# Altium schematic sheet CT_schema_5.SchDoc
size 278 x 170 mm
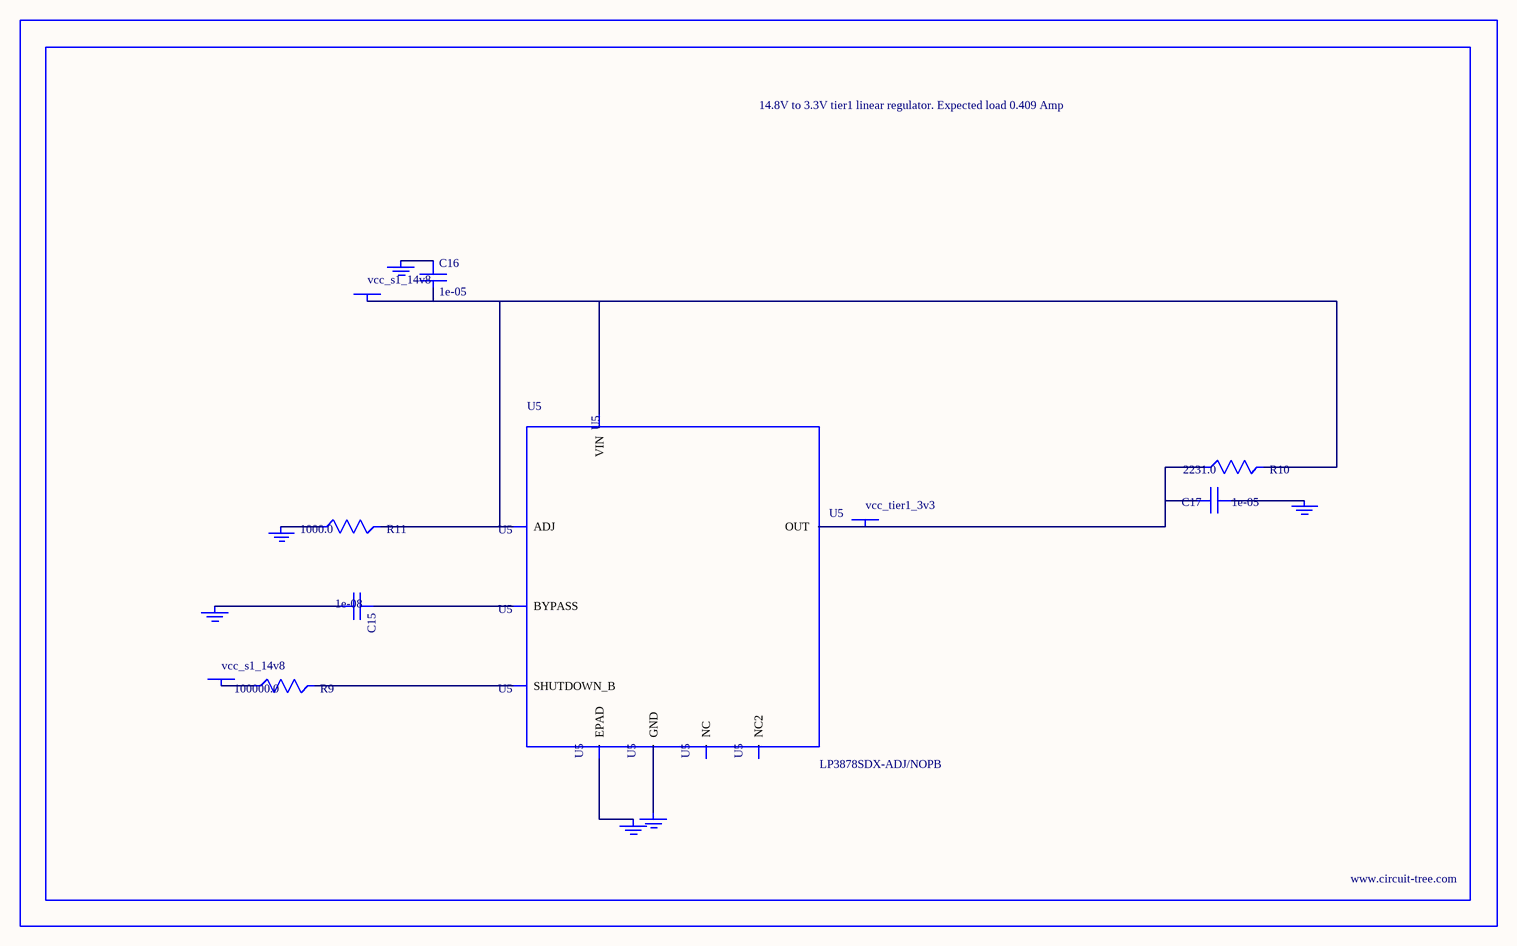
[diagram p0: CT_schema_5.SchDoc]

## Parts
BORDER4  (no value)
C15  1e-08  [C0402]
C16  1e-05  [C1210]
C17  1e-05  [C1210]
GND_INSTANCE_4_0  (no value)
GND_INSTANCE_4_1  (no value)
GND_INSTANCE_4_2  (no value)
GND_INSTANCE_4_3  (no value)
GND_INSTANCE_4_4  (no value)
GND_INSTANCE_4_5  (no value)
POWER_INSTANCE_4_0  vcc_s1_14v8
POWER_INSTANCE_4_1  vcc_s1_14v8
POWER_INSTANCE_4_2  vcc_tier1_3v3
R9  100000.0  [R0603]
R10  2231.0  [R0603]
R11  1000.0  [R0603]
U5  LP3878SDX-ADJ/NOPB  [WSON-8]

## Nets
NetC15_1: C15.1 U5.1(BYPASS)
NetC15_2: C15.2 GND_INSTANCE_4_0.0(GND)
NetC16_1: C16.1 GND_INSTANCE_4_1.0(GND)
NetC16_2: C16.2 POWER_INSTANCE_4_0.0(PWR) R10.2 R11.2 U5.4(VIN) U5.6(ADJ)
NetC17_1: C17.1 GND_INSTANCE_4_2.0(GND)
NetC17_2: C17.2 POWER_INSTANCE_4_2.0(PWR) R10.1 U5.5(OUT)
NetGND_INSTANCE_4_3_0: GND_INSTANCE_4_3.0(GND) R11.1
NetGND_INSTANCE_4_4_0: GND_INSTANCE_4_4.0(GND) U5.PAD(EPAD)
NetGND_INSTANCE_4_5_0: GND_INSTANCE_4_5.0(GND) U5.3(GND)
NetPOWER_INSTANCE_4_1_0: POWER_INSTANCE_4_1.0(PWR) R9.1
NetR9_2: R9.2 U5.8(SHUTDOWN_B)

Not connected (* = marked no-connect by the designer): U5 2(NC) 7(NC2)

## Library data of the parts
BORDER4 = BORDER_PAGE4
C15 = C0402C103K3RAC
C16 = C1210C106K5PACTU
C17 = GRM32DR61E106MA12L
GND_INSTANCE_4_0-GND_INSTANCE_4_5 = GND
POWER_INSTANCE_4_0-POWER_INSTANCE_4_2 = PWR
R9 = RC0603JR-07100KL
R10 = R10
R11 = RC0603JR-071KL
